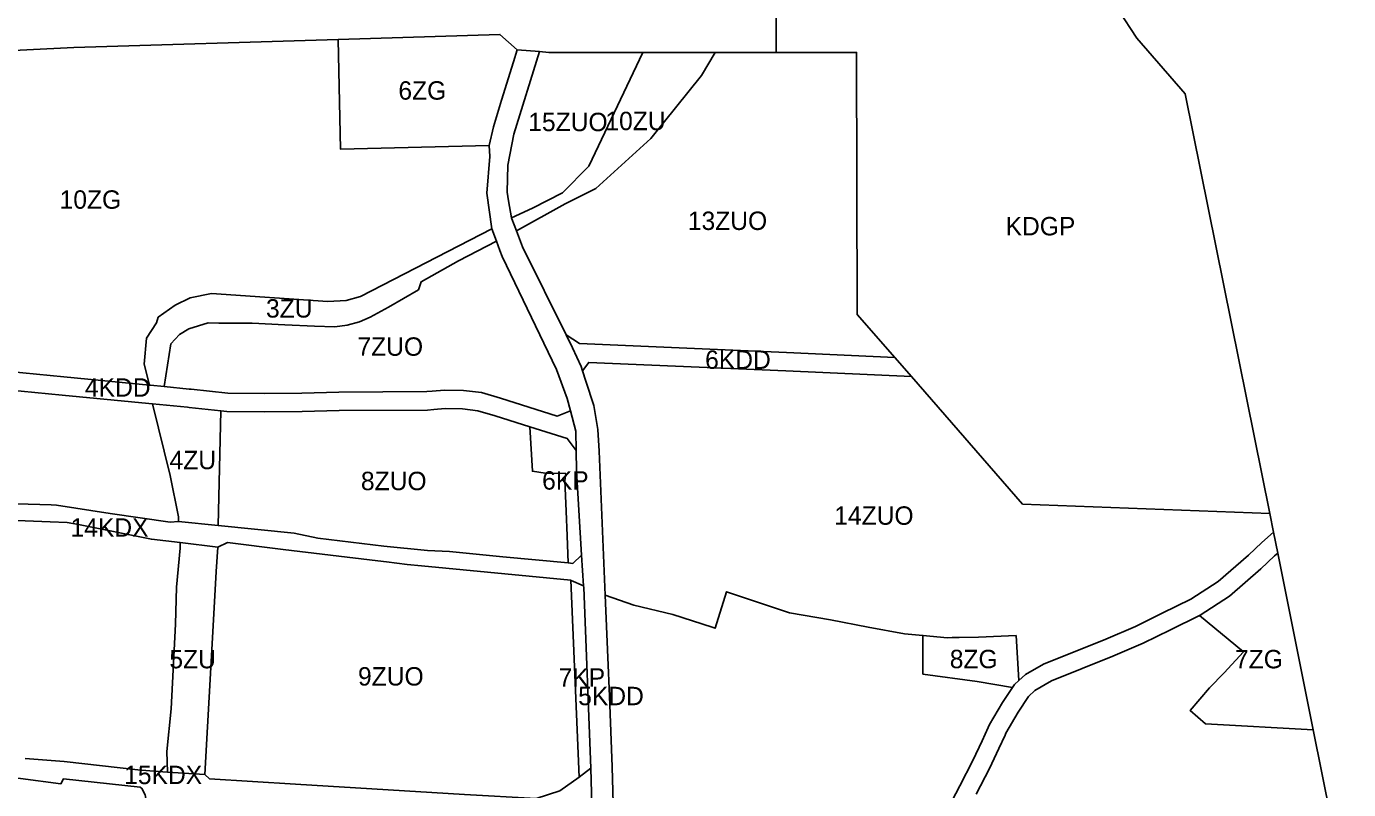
# Model space of a CAD drawing. Extents: x -300162 to -296646, y 29434 to 30761.
# Drawn here: x -297429 to -296711, y 29805 to 30220 of the extents above; entities that cross this region are included whole.
import ezdxf

# ---------------------------------------------------------------- set-up
doc = ezdxf.new("R2010")
doc.units = 0
doc.layers.add('linie_rozgraniczajace', color=7, linetype='Continuous')
doc.layers.add('oznaczenia_przeznaczen', color=7, linetype='Continuous')

msp = doc.modelspace()

# ---------------------------------------------------------------- linework, layer by layer
at = {"layer": 'linie_rozgraniczajace'}
for points in [[(-297590.776, 30224.231), (-297409.945, 30233.116), (-297408.054, 30233.2), (-297403.958, 30233.382), (-297348.879, 30235.158), (-297260.831, 30237.88), (-297174.211, 30245.488), (-297173.062, 30246.567), (-297152.53, 30265.841), (-297140.612, 30267.413), (-297127.414, 30253.817), (-297078.116, 30253.817), (-297040.258, 30253.817), (-297021.45, 30253.817), (-297021.45, 30205.815), (-297054.607, 30205.816), (-297093.914, 30205.817), (-297145.046, 30205.818), (-297150.146, 30206.255), (-297162.192, 30207.287), (-297171.547, 30215.628), (-297259.47, 30212.91), (-297403, 30208.4), (-297614.92, 30198.015)], [(-297614.92, 30198.015), (-297403, 30208.4), (-297259.47, 30212.91), (-297258.12, 30153.17), (-297177.35, 30155.18), (-297177.15, 30149.18), (-297178.72, 30129.26), (-297175.9, 30109.86), (-297247.28, 30073.1), (-297255.1, 30071.05), (-297265.12, 30070.38), (-297328.35, 30074.76), (-297339.92, 30072.45), (-297348.09, 30068.43), (-297357.27, 30061.88), (-297358.143, 30058.924), (-297363.54, 30050.526), (-297364.794, 30036.417), (-297361.996, 30025.085), (-297408.4, 30029.57), (-297468.03, 30035.37)], [(-297178.72, 30129.26), (-297177.15, 30149.18), (-297177.35, 30155.18), (-297175.15, 30165.35), (-297170.679, 30179.82), (-297164.243, 30200.651), (-297162.192, 30207.287), (-297150.146, 30206.255), (-297164.06, 30161.4), (-297167.37, 30144.46), (-297167.71, 30129.88), (-297166.889, 30125.159), (-297165.28, 30115.91), (-297165.09, 30115.41), (-297162.64, 30108.84), (-297159.37, 30100.09), (-297135.654, 30052.284), (-297132.14, 30045.2), (-297127.5, 30035.1), (-297126.763, 30032.808), (-297124.98, 30027.26), (-297120.5, 30014), (-297118.37, 30000.92), (-297117.69, 29989.09), (-297115, 29923.88), (-297114.44, 29910.87), (-297112.99, 29877.03), (-297112.1, 29856.09), (-297110.62, 29817.52), (-297109.29, 29771.26)], [(-297121.15, 29776.6), (-297122.15, 29816.8), (-297126.064, 29915), (-297126.1, 29915.9), (-297127.284, 29932.542), (-297129.9, 29978.51), (-297130.154, 29989.428), (-297130.4, 30000), (-297133.2, 30010.96), (-297134.982, 30017.759), (-297140.8, 30033.52), (-297170.3, 30094.87), (-297171.555, 30098.231), (-297173.411, 30103.199), (-297175.9, 30109.86), (-297178.72, 30129.26)], [(-297468.03, 30035.37), (-297408.4, 30029.57), (-297361.996, 30025.085), (-297361.32, 30025.02), (-297354.06, 30024.28), (-297340.36, 30022.9), (-297339.39, 30022.8), (-297319.43, 30020.7), (-297299.35, 30020.46), (-297279.26, 30020.7), (-297259.12, 30021.28), (-297211.35, 30021.48), (-297208.39, 30021.76), (-297201.63, 30022.3), (-297191.28, 30022.18), (-297181.55, 30020.95), (-297171.32, 30017.99), (-297140.5, 30008.18), (-297133.2, 30010.96), (-297130.4, 30000), (-297130.154, 29989.428), (-297135.042, 29995.948), (-297155.331, 30002.406), (-297174.227, 30008.421), (-297183.579, 30011.127), (-297191.967, 30012.187), (-297201.289, 30012.295), (-297207.521, 30011.798), (-297210.857, 30011.482), (-297258.955, 30011.281), (-297279.056, 30010.702), (-297299.35, 30010.459), (-297320.014, 30010.706), (-297323.179, 30011.039), (-297340.426, 30012.854), (-297341.374, 30012.952), (-297360.319, 30014.868), (-297362.282, 30015.066), (-297409.365, 30019.617), (-297468.984, 30025.416)], [(-297468.984, 30025.416), (-297409.365, 30019.617), (-297362.282, 30015.066), (-297360.319, 30014.868), (-297350.65, 29975.9), (-297346.12, 29953.45), (-297346.16, 29950.85), (-297350.78, 29950.53), (-297383.27, 29955.2), (-297412.48, 29959.81), (-297415.34, 29959.91), (-297434.09, 29960.59)], [(-297434.09, 29960.59), (-297415.34, 29959.91), (-297412.48, 29959.81), (-297383.27, 29955.2), (-297350.78, 29950.53), (-297346.16, 29950.85), (-297324.65, 29948.68), (-297283.37, 29944.66), (-297270.5, 29941.89), (-297234.661, 29937.537), (-297210.885, 29935.238), (-297199.06, 29934.53), (-297170.085, 29931.803), (-297134.57, 29928.46), (-297131.964, 29928.147), (-297127.284, 29932.542), (-297126.1, 29915.9), (-297132.88, 29918.94), (-297133.063, 29918.958), (-297214.164, 29926.843), (-297221.95, 29927.6), (-297233.155, 29928.959), (-297237.96, 29929.542), (-297289.3, 29935.77), (-297319.56, 29939.45), (-297324.9, 29937.02), (-297345.3, 29939.58), (-297360.89, 29941.25), (-297400.46, 29949.33), (-297406.58, 29950.31), (-297415.84, 29950.68), (-297438.49, 29951.58)], [(-297438.49, 29951.58), (-297415.84, 29950.68), (-297406.58, 29950.31), (-297400.46, 29949.33), (-297360.89, 29941.25), (-297345.3, 29939.58), (-297345.3, 29936.4), (-297347.25, 29915.3), (-297347.8, 29895.1), (-297350.2, 29849.15), (-297352.44, 29826.02), (-297352.2, 29814.72), (-297359.67, 29815.3), (-297368.26, 29815.97), (-297408.23, 29820.41), (-297429.5, 29822.07)], [(-296930.403, 29790.572), (-296921.689, 29807.279), (-296914.683, 29821.062), (-296909.602, 29831.811), (-296906.276, 29838.978), (-296905.58, 29840.546), (-296898.523, 29852.598), (-296893.191, 29860.711), (-296892.132, 29862.321), (-296889.713, 29864.49), (-296889.621, 29864.572), (-296885.987, 29867.746), (-296876.291, 29873.39), (-296842.391, 29886.976), (-296826.291, 29893.839), (-296811.797, 29901.017), (-296796.199, 29908.724), (-296781.331, 29918.338), (-296764.915, 29932.607), (-296757.591, 29939.566), (-296751.34, 29945.166), (-296749.052, 29933.79), (-296750.81, 29932.216), (-296758.188, 29925.205), (-296775.306, 29910.325), (-296791.253, 29900.014), (-296791.485, 29899.9), (-296807.363, 29892.053), (-296822.109, 29884.751), (-296838.569, 29877.734), (-296871.892, 29864.379), (-296880.956, 29859.103), (-296884.423, 29855.843), (-296890.024, 29847.322), (-296896.668, 29835.974), (-296897.171, 29834.842), (-296900.546, 29827.569), (-296905.704, 29816.658), (-296912.798, 29802.701)], [(-297109.29, 29771.26), (-297110.62, 29817.52), (-297112.1, 29856.09), (-297112.99, 29877.03), (-297114.44, 29910.87), (-297098.82, 29905.44), (-297077.6, 29900.32), (-297056.37, 29893.45), (-297054.68, 29892.89), (-297048.43, 29912.73), (-297014.29, 29901.27), (-296991.91, 29897.46), (-296971.54, 29893.55), (-296951.86, 29889.96), (-296941.811, 29889.013), (-296941.811, 29867.998), (-296912.39, 29863.95), (-296893.191, 29860.711), (-296898.523, 29852.598), (-296905.58, 29840.546), (-296906.276, 29838.978), (-296909.602, 29831.811), (-296914.683, 29821.062), (-296921.689, 29807.279), (-296930.403, 29790.572)], [(-296912.798, 29802.701), (-296905.704, 29816.658), (-296900.546, 29827.569), (-296897.171, 29834.842), (-296896.668, 29835.974), (-296890.024, 29847.322), (-296884.423, 29855.843), (-296880.956, 29859.103), (-296871.892, 29864.379), (-296838.569, 29877.734), (-296822.109, 29884.751), (-296807.363, 29892.053), (-296791.485, 29899.9), (-296767.69, 29880.18), (-296778.18, 29868.65), (-296786.08, 29860.44), (-296796.55, 29848.13), (-296788.263, 29841.042), (-296729.718, 29837.66), (-296710.569, 29742.447)], [(-297429.5, 29822.07), (-297408.23, 29820.41), (-297368.26, 29815.97), (-297359.67, 29815.3), (-297352.2, 29814.72), (-297331.83, 29813.38), (-297329.3, 29811.14), (-297282.65, 29808.12), (-297190.84, 29802.58)], [(-297454.12, 29814.24), (-297410.06, 29808.44), (-297408.74, 29811.08), (-297366.96, 29806.51), (-297366.02, 29805.88), (-297364.28, 29802.43), (-297362.88, 29794.13), (-297363.84, 29785.56), (-297369.7, 29733.54), (-297371.58, 29719.01), (-297375.95, 29708.67), (-297382.09, 29704.83), (-297390.88, 29705.09), (-297480.15, 29719.3)], [(-297364.28, 29802.43), (-297366.02, 29805.88), (-297366.96, 29806.51), (-297408.74, 29811.08), (-297410.06, 29808.44), (-297454.12, 29814.24)], [(-297139.12, 29804.55), (-297128.6, 29811.97), (-297122.15, 29816.8), (-297121.15, 29776.6)]]:
    msp.add_lwpolyline(points, dxfattribs=at)
for points in [[(-297021.45, 30205.815), (-297021.45, 30253.817), (-296982.702, 30253.817), (-296960.128, 30253.817), (-296942.869, 30253.817), (-296918.263, 30252.578), (-296844.452, 30272.019), (-296843.422, 30256.841), (-296842.987, 30253.169), (-296840.553, 30240.904), (-296835.532, 30228.696), (-296825.516, 30213.542), (-296799.251, 30183.385), (-296753.354, 29955.178), (-296887.679, 29960.347), (-296948.059, 30029.672), (-296957.135, 30040.092), (-296977.45, 30063.416), (-296977.798, 30205.814)], [(-297259.47, 30212.91), (-297171.547, 30215.628), (-297162.192, 30207.287), (-297164.243, 30200.651), (-297170.679, 30179.82), (-297175.15, 30165.35), (-297177.35, 30155.18), (-297258.12, 30153.17)], [(-297167.71, 30129.88), (-297167.37, 30144.46), (-297164.06, 30161.4), (-297150.146, 30206.255), (-297145.046, 30205.818), (-297093.914, 30205.817), (-297123.34, 30144.05), (-297137.65, 30129.57), (-297153.89, 30121.25), (-297165.28, 30115.91), (-297166.889, 30125.159)], [(-297165.28, 30115.91), (-297153.89, 30121.25), (-297137.65, 30129.57), (-297123.34, 30144.05), (-297093.914, 30205.817), (-297054.607, 30205.816), (-297062, 30193.2), (-297089.6, 30159), (-297119.45, 30131.8), (-297136.19, 30123.61), (-297162.64, 30108.84), (-297165.09, 30115.41)], [(-297162.64, 30108.84), (-297136.19, 30123.61), (-297119.45, 30131.8), (-297089.6, 30159), (-297062, 30193.2), (-297054.607, 30205.816), (-297021.45, 30205.815), (-296977.798, 30205.814), (-296977.45, 30063.416), (-296957.135, 30040.092), (-297015.839, 30042.745), (-297128.437, 30047.59), (-297135.654, 30052.284), (-297159.37, 30100.09)], [(-297364.794, 30036.417), (-297363.54, 30050.526), (-297358.143, 30058.924), (-297357.27, 30061.88), (-297348.09, 30068.43), (-297339.92, 30072.45), (-297328.35, 30074.76), (-297265.12, 30070.38), (-297255.1, 30071.05), (-297247.28, 30073.1), (-297175.9, 30109.86), (-297173.411, 30103.199), (-297194.1, 30092.6), (-297214.37, 30081.17), (-297215.86, 30076.85), (-297232.12, 30067.32), (-297241.98, 30061.95), (-297247.81, 30059.5), (-297254.51, 30057.6), (-297261.28, 30056.78), (-297272.26, 30056.98), (-297288.45, 30057.86), (-297306.19, 30058.72), (-297317.32, 30058.74), (-297324.28, 30058.68), (-297330.04, 30058.86), (-297340.62, 30055.55), (-297345.66, 30052.59), (-297350.31, 30047.37), (-297354.06, 30024.28), (-297361.32, 30025.02), (-297361.996, 30025.085)], [(-297354.06, 30024.28), (-297350.31, 30047.37), (-297345.66, 30052.59), (-297340.62, 30055.55), (-297330.04, 30058.86), (-297324.28, 30058.68), (-297317.32, 30058.74), (-297306.19, 30058.72), (-297288.45, 30057.86), (-297272.26, 30056.98), (-297261.28, 30056.78), (-297254.51, 30057.6), (-297247.81, 30059.5), (-297241.98, 30061.95), (-297232.12, 30067.32), (-297215.86, 30076.85), (-297214.37, 30081.17), (-297194.1, 30092.6), (-297173.411, 30103.199), (-297171.555, 30098.231), (-297170.3, 30094.87), (-297140.8, 30033.52), (-297134.982, 30017.759), (-297133.2, 30010.96), (-297140.5, 30008.18), (-297171.32, 30017.99), (-297181.55, 30020.95), (-297191.28, 30022.18), (-297201.63, 30022.3), (-297208.39, 30021.76), (-297211.35, 30021.48), (-297259.12, 30021.28), (-297279.26, 30020.7), (-297299.35, 30020.46), (-297319.43, 30020.7), (-297339.39, 30022.8), (-297340.36, 30022.9)], [(-297135.654, 30052.284), (-297128.437, 30047.59), (-297015.839, 30042.745), (-296957.135, 30040.092), (-296948.059, 30029.672), (-297016.28, 30032.755), (-297123.326, 30037.361), (-297126.763, 30032.808), (-297127.5, 30035.1), (-297132.14, 30045.2)], [(-297126.763, 30032.808), (-297123.326, 30037.361), (-297016.28, 30032.755), (-296948.059, 30029.672), (-296887.679, 29960.347), (-296753.354, 29955.178), (-296751.34, 29945.166), (-296757.591, 29939.566), (-296764.915, 29932.607), (-296781.331, 29918.338), (-296796.199, 29908.724), (-296811.797, 29901.017), (-296826.291, 29893.839), (-296842.391, 29886.976), (-296876.291, 29873.39), (-296885.987, 29867.746), (-296889.621, 29864.572), (-296889.713, 29864.49), (-296891.17, 29888.88), (-296911.61, 29888.06), (-296922.1, 29887.87), (-296925.98, 29887.79), (-296928.41, 29887.75), (-296941.811, 29889.013), (-296951.86, 29889.96), (-296971.54, 29893.55), (-296991.91, 29897.46), (-297014.29, 29901.27), (-297048.43, 29912.73), (-297054.68, 29892.89), (-297056.37, 29893.45), (-297077.6, 29900.32), (-297098.82, 29905.44), (-297114.44, 29910.87), (-297115, 29923.88), (-297117.69, 29989.09), (-297118.37, 30000.92), (-297120.5, 30014), (-297124.98, 30027.26)], [(-297360.319, 30014.868), (-297341.374, 30012.952), (-297340.426, 30012.854), (-297323.179, 30011.039), (-297324.65, 29948.68), (-297346.16, 29950.85), (-297346.12, 29953.45), (-297350.65, 29975.9)], [(-297324.65, 29948.68), (-297323.179, 30011.039), (-297320.014, 30010.706), (-297299.35, 30010.459), (-297279.056, 30010.702), (-297258.955, 30011.281), (-297210.857, 30011.482), (-297207.521, 30011.798), (-297201.289, 30012.295), (-297191.967, 30012.187), (-297183.579, 30011.127), (-297174.227, 30008.421), (-297155.331, 30002.406), (-297153.97, 29978.23), (-297146.95, 29977.11), (-297135.85, 29976.97), (-297136.259, 29973.232), (-297135.65, 29956.612), (-297135.056, 29943.066), (-297134.57, 29928.46), (-297170.085, 29931.803), (-297199.06, 29934.53), (-297210.885, 29935.238), (-297234.661, 29937.537), (-297270.5, 29941.89), (-297283.37, 29944.66)], [(-297155.331, 30002.406), (-297135.042, 29995.948), (-297130.154, 29989.428), (-297129.9, 29978.51), (-297127.284, 29932.542), (-297131.964, 29928.147), (-297134.57, 29928.46), (-297135.056, 29943.066), (-297135.65, 29956.612), (-297136.259, 29973.232), (-297135.85, 29976.97), (-297146.95, 29977.11), (-297153.97, 29978.23)], [(-297352.44, 29826.02), (-297350.2, 29849.15), (-297347.8, 29895.1), (-297347.25, 29915.3), (-297345.3, 29936.4), (-297345.3, 29939.58), (-297324.9, 29937.02), (-297325.648, 29923.681), (-297327.66, 29887.78), (-297330.378, 29839.293), (-297331.83, 29813.38), (-297352.2, 29814.72)], [(-297331.83, 29813.38), (-297330.378, 29839.293), (-297327.66, 29887.78), (-297325.648, 29923.681), (-297324.9, 29937.02), (-297319.56, 29939.45), (-297289.3, 29935.77), (-297237.96, 29929.542), (-297233.155, 29928.959), (-297221.95, 29927.6), (-297214.164, 29926.843), (-297133.063, 29918.958), (-297128.6, 29811.97), (-297139.12, 29804.55), (-297151.81, 29800.41), (-297190.84, 29802.58), (-297282.65, 29808.12), (-297329.3, 29811.14)], [(-296796.55, 29848.13), (-296786.08, 29860.44), (-296778.18, 29868.65), (-296767.69, 29880.18), (-296791.485, 29899.9), (-296791.253, 29900.014), (-296775.306, 29910.325), (-296758.188, 29925.205), (-296750.81, 29932.216), (-296749.052, 29933.79), (-296729.718, 29837.66), (-296788.263, 29841.042)], [(-297133.063, 29918.958), (-297132.88, 29918.94), (-297126.1, 29915.9), (-297126.064, 29915), (-297122.15, 29816.8), (-297128.6, 29811.97)], [(-296941.811, 29867.998), (-296941.811, 29889.013), (-296928.41, 29887.75), (-296925.98, 29887.79), (-296922.1, 29887.87), (-296911.61, 29888.06), (-296891.17, 29888.88), (-296889.713, 29864.49), (-296892.132, 29862.321), (-296893.191, 29860.711), (-296912.39, 29863.95)]]:
    msp.add_lwpolyline(points, close=True, dxfattribs=at)

# ---------------------------------------------------------------- texts
at = {"layer": 'oznaczenia_przeznaczen'}
for s, p in [('6ZG', (-297226.732044, 30180.140001)), ('15ZUO', (-297156.193694, 30163.020001)), ('10ZU', (-297114.272022, 30163.560001)), ('10ZG', (-297410.776866, 30120.860001)), ('13ZUO', (-297069.497694, 30109.330001)), ('KDGP', (-296896.895167, 30106.390001)), ('3ZU', (-297298.655459, 30061.720001)), ('7ZUO', (-297248.982596, 30040.970001)), ('6KDD', (-297060.103167, 30033.850001)), ('4KDD', (-297397.017425, 30018.750001)), ('4ZU', (-297351.041459, 29979.330001)), ('8ZUO', (-297247.092596, 29967.940001)), ('6KP', (-297148.654303, 29968.230001)), ('14ZUO', (-296989.973694, 29949.140001)), ('14KDX', (-297404.843679, 29942.670001)), ('5ZU', (-297351.141459, 29871.140001)), ('8ZG', (-296927.216303, 29871.190001)), ('7ZG', (-296772.256303, 29871.120001)), ('9ZUO', (-297248.667752, 29861.770001)), ('7KP', (-297139.698561, 29861.160001)), ('5KDD', (-297129.067425, 29851.090001)), ('15KDX', (-297375.703679, 29808.210001))]:
    msp.add_text(s, height=10, dxfattribs=at).set_placement(p)

doc.saveas('drawing.dxf')
